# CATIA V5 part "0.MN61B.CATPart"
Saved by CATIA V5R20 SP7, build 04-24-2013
Part number: 0.MN61B
Material "Nessuno"
Bounding box of the stored display mesh (mm): x 0 to 149.213, y -131.181 to 0, z -56.919 to 41.584
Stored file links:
  C:\Users\designer2\Desktop\Ottobre 2022\25-10-2022\04\Yori Evo 48V\0.MN61B.CATPart
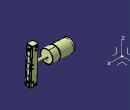
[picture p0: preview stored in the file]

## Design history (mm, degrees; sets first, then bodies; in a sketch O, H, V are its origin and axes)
AxisSystem1: origin (0, 0, 0), X (1, 0, 0), Y (0, 1, 0), Z (0, 0, 1)
Set1
  DatumSurface1
Body1 (main body), material "Nessuno"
